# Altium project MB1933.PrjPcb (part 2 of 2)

## Sheet USB-C_Device.SchDoc: USB-C_Device
size A4; Date: Not used; ApprovedBy: Not used; CheckedBy: Not used; Author: Not used; CompanyName: STMicroelectronics; DrawnBy: Not used; Engineer: Not used; Organization: Not used; Address1: Not used; Address2: Not used; Address3: Not used; Address4: Not used; DocumentNumber: Not used; Revision: V0.1; SheetNumber: 5; SheetTotal: 11
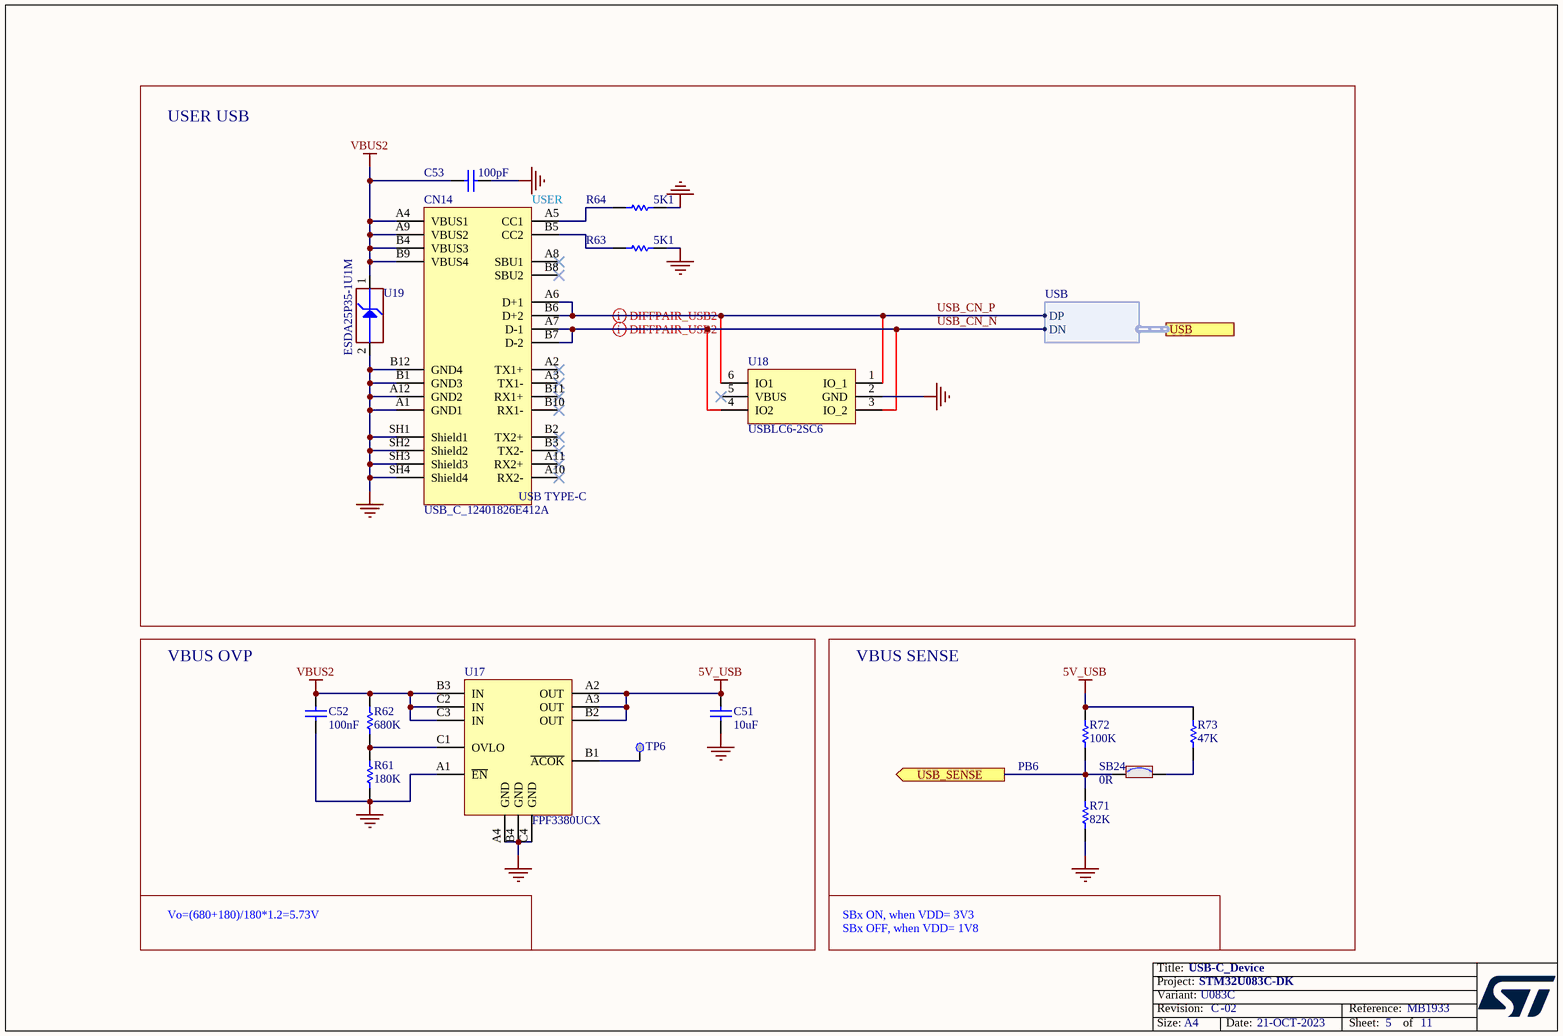
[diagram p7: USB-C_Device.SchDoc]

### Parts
C51  value 10uF  [C0603]  (hidden comment: Capacitor)
C52  value 100nF  [C0603]  (hidden comment: Capacitor)
C53  value 100pF  [C0402]  (hidden comment: Capacitor)
CN14  value USB_C_12401826E412A  [CON_USB-TYPEC_AMPHENOL_12401826E412A]  (hidden comment: USB_TYPE_C_Receptacle)
R61  value 180K  [R0402]  (hidden comment: Resistor)
R62  value 680K  [R0402]  (hidden comment: Resistor)
R63  value 5K1  [R0402]  (hidden comment: Resistor)
R64  value 5K1  [R0402]  (hidden comment: Resistor)
R71  value 82K  [R0402]  (hidden comment: Resistor)
R72  value 100K  [R0402]  (hidden comment: Resistor)
R73  value 47K  [R0402]  (hidden comment: Resistor)
SB24  value 0R  [SOLDER-BRIDGE_R0603-0R]  (hidden comment: SB_ON)
TP6  Test Point  [TP_SMD_1MM]  (value not drawn)  (no BOM)
U17  value FPF3380UCX  [ICC_WLCSP12_1P858x1P318_P040]  (hidden comment: AW329xxFCR)
U18  USBLC6-2SC6  [ESD_SOT23-6L]
U19  value ESDA25P35-1U1M  [ESD_QFN1610_2N_1K_2A]  (hidden comment: ESD-TRANSIL)

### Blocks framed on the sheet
USER USB: C53 CN14 R63 R64 U18 U19
VBUS OVP: C51 C52 R61 R62 TP6 U17
VBUS SENSE: R71-R73 SB24

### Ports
USB (harness USB), USB_SENSE (out)

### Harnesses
USB: DP, DN

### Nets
5V_USB: C51.2 R72.2 R73.2 U17.A2(OUT) U17.A3(OUT) U17.B2(OUT)
GND: C51.1 C52.2 C53.2 CN14.A1(GND1) CN14.A12(GND2) CN14.B1(GND3) CN14.B12(GND4) CN14.SH1(Shield1) CN14.SH2(Shield2) CN14.SH3(Shield3) CN14.SH4(Shield4) R61.1 R63.2 R64.2 R71.1 U17.A1(~{EN}) U17.A4(GND) U17.B4(GND) U17.C4(GND) U18.2(GND) U19.2(GND)
VBUS2: C52.1 C53.1 CN14.A4(VBUS1) CN14.A9(VBUS2) CN14.B4(VBUS3) CN14.B9(VBUS4) R62.2 U17.B3(IN) U17.C2(IN) U17.C3(IN) U19.1(IO1)
ARD_D8: R71.2 R72.1 SB24.1 ; port USB_SENSE
USB_CN_N: CN14.A7(D-1) CN14.B7(D-2) U18.3(IO_2) U18.4(IO2) ; port USB.DN  [project net PA11]
USB_CN_P: CN14.A6(D+1) CN14.B6(D+2) U18.1(IO_1) U18.6(IO1) ; port USB.DP  [project net PA12]
NetCN14_A5: CN14.A5(CC1) R64.1
NetCN14_B5: CN14.B5(CC2) R63.1
NetR61_2: R61.2 R62.1 U17.C1(OVLO)
NetR73_1: R73.1 SB24.2
NetTP6_1: TP6.1 U17.B1(~{ACOK})

Not connected (* = marked no-connect by the designer): CN14 A2(TX1+)* A3(TX1-)* A8(SBU1)* A10(RX2-)* A11(RX2+)* B2(TX2+)* B3(TX2-)* B8(SBU2)* B10(RX1-)* B11(RX1+)*; U18 5(VBUS)*

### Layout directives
differential pair; rule Impedance Constraint [Min = 85.00    Max = 95.00    ]: PA11, PA12

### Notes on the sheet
- (near CN14) USER
- PB6
- Vo=(680+180)/180*1.2=5.73V
- SBx ON, when VDD= 3V3
- SBx OFF, when VDD= 1V8

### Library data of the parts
C51 = MCD-00099: Capacitor, MLCC, 10uF, 10V, X5R, +/-10%, 0603, T=0.8mm; Part_Preference: Recommended; Manufacturer: MURATA; Manufacturer_Part_Number: GRM188R61A106KE69D; Partial_Alternate_Internal_Part_Number: MCD-03152; Order_Code_RS: 2494233; Component_Country_Of_Origin: Japan°°; ShowFields: YES; ID: 2770
C52 = MCD-01099: Capacitor, MLCC, 100nF, 50V, X7R, +/-10%, 0603, T=0.8mm; Manufacturer_Part_Number: CC0603KRX7R9BB104; Manufacturer: YAGEO; BMS_Part_Number: 9142278; Part_Preference: Recommended; Order_Code_RS: 669-8767; Component_Country_Of_Origin: China; ShowFields: YES; ID: 3397
C53 = MCD-00205: Capacitor, MLCC, 100pF, 50V, NPO, +/-5%, 0402, T=0.5mm; Part_Preference: Recommended; Manufacturer: YAGEO; Manufacturer_Part_Number: CC0402JRNPO9BN101; Component_Country_Of_Origin: China; ShowFields: YES; ID: 2658
CN14 = MCD-03232: USB_TypeC, 24 pins, RA, SMD, T=2.96mm; Part_Type: Connector; Part_Preference: Recommended; Manufacturer: AMPHENOL ICC; Manufacturer_Part_Number: 12401826E412A; Component_Country_Of_Origin: China°; ShowFields: YES; ID: 5348
R61 = MCD-00413: Resistor, 180K, 0402, +/-1%, 1/16W; Manufacturer_Part_Number: RC0402FR-07180KL; Manufacturer: YAGEO; Part_Preference: Recommended; Component_Country_Of_Origin: China; ShowFields: YES; ID: 2864
R62 = MCD-00513: Resistor, 680K, 0402, +/-1%, 1/16W; Manufacturer_Part_Number: RC0402FR-07680KL; Manufacturer: YAGEO; Part_Preference: Recommended; Component_Country_Of_Origin: China; ShowFields: YES; ID: 3227
R63 R64 = MCD-00333: Resistor, 5K1, 0402, +/-1%, 1/16W; Part_Preference: Recommended; Manufacturer: YAGEO; Manufacturer_Part_Number: RC0402FR-075K1L; Component_Country_Of_Origin: China; ShowFields: YES; ID: 2944
R71 = MCD-00531: Resistor, 82K, 0402, +/-1%, 1/16W; Part_Preference: Recommended; Manufacturer: YAGEO; Manufacturer_Part_Number: RC0402FR-0782KL; Component_Country_Of_Origin: China; ShowFields: YES; ID: 3207
R72 = MCD-00059: Resistor, 100K, 0402, +/-1%, 1/16W; Part_Preference: Recommended; Manufacturer: YAGEO; Manufacturer_Part_Number: RC0402FR-07100KL; Partial_Alternate_Internal_Part_Number: MCD-03301; Order_Code_RS: 2421891; Component_Country_Of_Origin: China; ShowFields: YES; ID: 2533
R73 = MCD-00063: Resistor, 47K, 0402, +/-1%, 1/16W; Part_Preference: Recommended; Manufacturer: YAGEO; Manufacturer_Part_Number: RC0402FR-0747KL; Order_Code_RS: 9239430; Component_Country_Of_Origin: China; ShowFields: YES; ID: 2528
SB24 = MCD-00071: Resistor, 0R, SB0603, 5%, 0.1W; Manufacturer_Part_Number: RC0603JR-070RL; Manufacturer: YAGEO; Part_Preference: Recommended; Manufacturer_HQ_COO: Unknown; ShowFields: YES; ID: 2521; Order_Code_RS: 199-5647; Component_Country_Of_Origin: China
TP6 = MCD-00074: Test Point 1mm; Part_Type: Misc; Part_Preference: Recommended; ShowFields: YES; ID: 2518; Component_Country_Of_Origin: Unknown
U17 = MCD-03166: Power switch, 28 V / 5 A  OVP with Low On-resistance, Integrated TVS; Part_Type: IC; Part_Preference: Recommended; Manufacturer: ON SEMICONDUCTOR; Partial_Alternate_Internal_Part_Number: MCD-03058; ShowFields: YES; ID: 5282; Component_Country_Of_Origin: Philippines
U18 = MCD-00163: Very low capacitance ESD protection; Part_Type: IC; Manufacturer: STMICROELECTRONICS; BMS_Part_Number: 9151075; Part_Preference: Recommended; Manufacturer_HQ_COO: EU; Component_Country_Of_Origin: China; ShowFields: YES; ID: 2707
U19 = MCD-01207: Diode, ESD TVS, 22V, 200nA, 25V8, QFN1610; Manufacturer: STMICROELECTRONICS; BMS_Part_Number: 9179045; Part_Preference: Recommended; Manufacturer_HQ_COO: EU; Component_Country_Of_Origin: China; ShowFields: YES; ID: 3289; Order_Code_RS: 163-9774

## Sheet PERIPHERAL.SchDoc: PERIPHERAL
size A4; Date: Not used; ApprovedBy: Not used; CheckedBy: Not used; Author: Not used; CompanyName: STMicroelectronics; DrawnBy: Not used; Engineer: Not used; Organization: Not used; Address1: Not used; Address2: Not used; Address3: Not used; Address4: Not used; DocumentNumber: 10; Revision: Not used; SheetNumber: 7; SheetTotal: 11
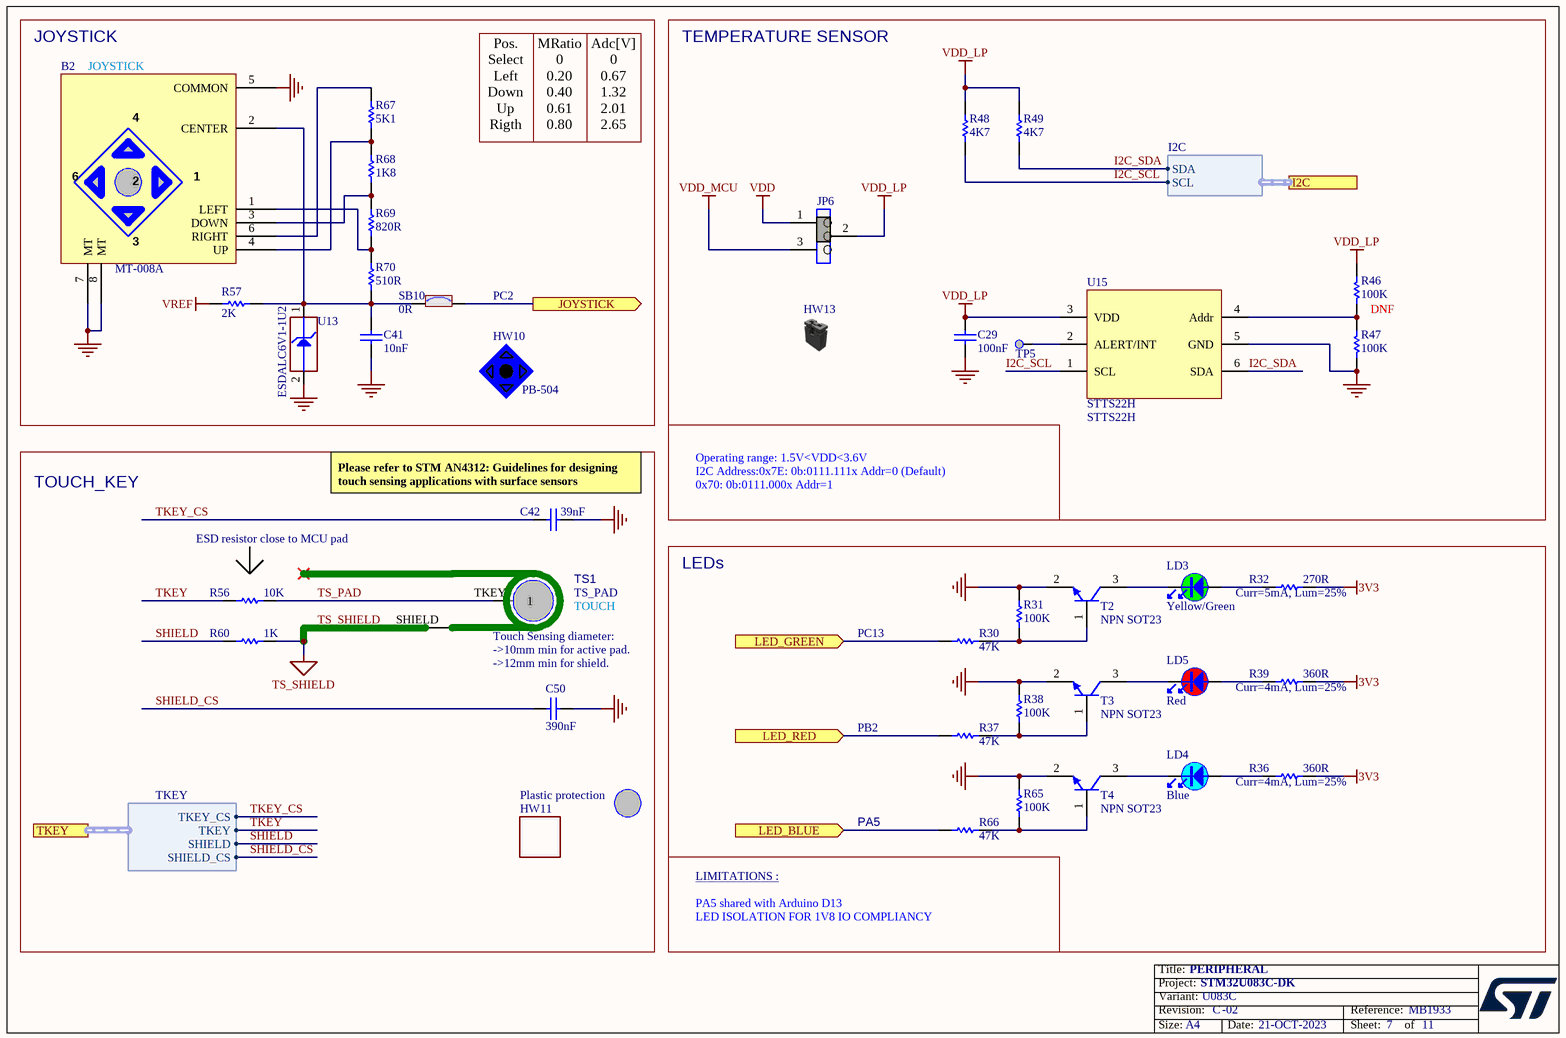
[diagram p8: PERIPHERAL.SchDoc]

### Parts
B2  value MT-008A  [SWI_XIEJIA_MT-008A_6P]  (hidden comment: Joystick MT-008A_M)
C29  value 100nF  [C0402]  (hidden comment: Capacitor)
C41  value 10nF  [C0402]  (hidden comment: Capacitor)
C42  value 39nF  [C1206_H0P85]  (hidden comment: Capacitor)
C50  value 390nF  [C0402]  (hidden comment: Capacitor)
HW10  value PB-504  (hidden comment: JOYSTICK_BLUE_HAT)  (mechanical)
HW11  value Plastic protection  (hidden comment: TouchKey sensitive Plastic protection)  (mechanical)
HW13  Shunt Black 2.54mm  (value not drawn)  (mechanical)
JP6  Jumper_Header 3x1 Fitted 1-2  [CON_SAMTEC_TSW-103-07-F-S]  (value not drawn)
LD3  value Yellow/Green  [LED_0402_EVERLIGHT_16-213SYGC/S530-E3-TR8 _YELLOW-GREEN_1A2K_H0P45]  (hidden comment: LED_green)
LD4  value Blue  [LED_0402_KINGBRIGHT_KPHHS-1005QBC-D-V_BLUE_1A2K_H0P5]  (hidden comment: LED_blue)
LD5  value Red  [LED_0402_KINGBRIGHT_KPHHS-1005SURCK_HYPER-RED_1A2K_H0P5]  (hidden comment: LED_red)
R30  value 47K  [R0402]  (hidden comment: Resistor)
R31  value 100K  [R0402]  (hidden comment: Resistor)
R32  value 270R  [R0402]  (hidden comment: Resistor)
R36  value 360R  [R0402]  (hidden comment: Resistor)
R37  value 47K  [R0402]  (hidden comment: Resistor)
R38  value 100K  [R0402]  (hidden comment: Resistor)
R39  value 360R  [R0402]  (hidden comment: Resistor)
R46  value 100K  [R0402]  (hidden comment: Resistor)
R47  value 100K  [R0402]  (hidden comment: Resistor)
R48  value 4K7  [R0402]  (hidden comment: Resistor)
R49  value 4K7  [R0402]  (hidden comment: Resistor)
R56  value 10K  [R0402]  (hidden comment: Resistor)
R57  value 2K  [R0402]  (hidden comment: Resistor)
R60  value 1K  [R0402]  (hidden comment: Resistor)
R65  value 100K  [R0402]  (hidden comment: Resistor)
R66  value 47K  [R0402]  (hidden comment: Resistor)
R67  value 5K1  [R0402]  (hidden comment: Resistor)
R68  value 1K8  [R0402]  (hidden comment: Resistor)
R69  value 820R  [R0402]  (hidden comment: Resistor)
R70  value 510R  [R0402]  (hidden comment: Resistor)
SB10  value 0R  [SOLDER-BRIDGE_R0603-0R]  (hidden comment: SB_ON)
T2  value NPN SOT23  [NPN_SOT23]  (hidden comment: 9013-SOT23)
T3  value NPN SOT23  [NPN_SOT23]  (hidden comment: 9013-SOT23)
T4  value NPN SOT23  [NPN_SOT23]  (hidden comment: 9013-SOT23)
TP5  Test Point  [TP_SMD_1MM]  (value not drawn)  (no BOM)
TS1  TS_PAD  [TSB_TOUCH-SENSING-BUTTON_TS-PAD-10_SHIELD-14]  (no BOM)
U13  value ESDALC6V1-1U2  [ESD_ST0201]  (hidden comment: ESD-TRANSIL)
U15  STTS22H  [ICC_UDFN6-EPAD_2X2_P065]

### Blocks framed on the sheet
JOYSTICK: B2 C41 HW10 R57 R67-R70 SB10 U13
TEMPERATURE SENSOR: C29 HW13 JP6 R46-R49 TP5 U15
TOUCH_KEY: C42 C50 HW11 R56 R60 TS1
LEDs: LD3-LD5 R30-R32 R36-R39 R65 R66 T2-T4

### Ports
I2C (harness I2C), JOYSTICK (out), LED_BLUE (in), LED_GREEN (in), LED_RED (in), TKEY (harness TKEY)

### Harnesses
I2C: SDA, SCL
TKEY: TKEY_CS, TKEY, SHIELD, SHIELD_CS

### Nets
3V3: R32.2 R36.2 R39.2
GND: B2.5(COMMON) B2.7(MT) B2.8(MT) C29.1 C41.1 C42.2 C50.2 R31.1 R38.1 R47.1 R65.1 T2.2(E) T3.2(E) T4.2(E) U13.2(GND) U15.5(GND)
TS_SHIELD: R60.2 TS1.SHIELD
VDD: JP6.1
VDD_LP: C29.2 JP6.2 R46.2 R48.2 R49.2 U15.3(VDD)
VDD_MCU: JP6.3
VREF: R57.1
ARD_D13: R66.1 ; port LED_BLUE
I2C_SCL: R48.1 U15.1(SCL) ; port I2C.SCL
I2C_SDA: R49.1 U15.6(SDA) ; port I2C.SDA
PB2: R37.1 ; port LED_RED
PC2: SB10.2 ; port JOYSTICK
PC13: R30.1 ; port LED_GREEN
SHIELD: R60.1 ; port TKEY.SHIELD  [project net PB12]
SHIELD_CS: C50.1 ; port TKEY.SHIELD_CS  [project net PB13]
TKEY: R56.1 ; port TKEY.TKEY  [project net PD11]
TKEY_CS: C42.1 ; port TKEY.TKEY_CS  [project net PD10]
TS_PAD: R56.2 TS1.TKEY(1)
NetB2_1: B2.1(LEFT) R69.1 R70.2
NetB2_2: B2.2(CENTER) C41.2 R57.2 R70.1 SB10.1 U13.1(IO1)
NetB2_3: B2.3(DOWN) R68.1 R69.2
NetB2_4: B2.4(UP) R67.1 R68.2
NetB2_6: B2.6(RIGHT) R67.2
NetLD3_1: LD3.1 R32.1
NetLD3_2: LD3.2 T2.3(C)
NetLD4_1: LD4.1 R36.1
NetLD4_2: LD4.2 T4.3(C)
NetLD5_1: LD5.1 R39.1
NetLD5_2: LD5.2 T3.3(C)
NetR30_2: R30.2 R31.2 T2.1(B)
NetR37_2: R37.2 R38.2 T3.1(B)
NetR46_1: R46.1 R47.2 U15.4(Addr)
NetR65_2: R65.2 R66.2 T4.1(B)
NetTP5_1: TP5.1 U15.2(ALERT/INT)

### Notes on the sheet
- (near B2) JOYSTICK
- Pos.
  Select
  Left
  Down
  Up
  Rigth
- MRatio
  0
  0.20
  0.40
  0.61
  0.80
- Adc[V]
  0
  0.67
  1.32
  2.01
  2.65
- PC2
- DNF
- (near C42) Please refer to STM AN4312: Guidelines for designing touch sensing applications with surface sensors
- I2C Address:0x7E: 0b:0111.111x Addr=0 (Default)
- 0x70: 0b:0111.000x Addr=1
- Operating range: 1.5V<VDD<3.6V
- ESD resistor close to MCU pad
- TOUCH
- PC13
- (near R32) Curr=5mA, Lum=25%
- (near TS1) Touch Sensing diameter:
  ->10mm min for active pad.
  ->12mm min for shield.
- (near R39) Curr=4mA, Lum=25%
- PB2
- (near R36) Curr=4mA, Lum=25%
- PA5
- LED ISOLATION FOR 1V8 IO COMPLIANCY
- PA5 shared with Arduino D13
- LIMITATIONS :

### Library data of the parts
B2 = MCD-00132: Joystick, Black hat; BMS_Part_Number: 9180124; Part_Preference: Recommended; Part_Type: Misc; Manufacturer: XIEJIA ELECTRONICS; Component_Country_Of_Origin: Unknown; ShowFields: YES; ID: 2736
C29 = MCD-00006: Capacitor, MLCC, 100nF, 16V, X7R, +/-10%, 0402, T=0.5mm; Manufacturer_Part_Number: CC0402KRX7R7BB104; Manufacturer: YAGEO; Part_Preference: Recommended; Partial_Alternate_Internal_Part_Number: MCD-03299; Order_Code_RS: 9402047; Component_Country_Of_Origin: China; ShowFields: YES; ID: 2474
C41 = MCD-02198: Capacitor, MLCC, 10nF, 50V, X7R, +/-10%, 0402, T=0.5mm; Manufacturer_Part_Number: CC0402KRX7R9BB103; Manufacturer: YAGEO; Part_Preference: Recommended; Order_Code_RS: 6169644; Component_Country_Of_Origin: China; ShowFields: YES; ID: 4298
C42 = MCD-01939: Capacitor, MLCC, 39nF, 50V, COG, +/-5%, 1206, T=0.85mm; Manufacturer_Part_Number: GRM3195C1H393JA01D; Manufacturer: MURATA; Part_Preference: Recommended; Component_Country_Of_Origin: Japan; ShowFields: YES; ID: 4039
C50 = MCD-02154: Capacitor, MLCC, 390nF, 10V, X5R, +/-10%, 0402, T=0.5mm; Manufacturer_Part_Number: GMD155R61A394KE11J; Manufacturer: MURATA; Part_Preference: Recommended; Order_Code_RS: N\A; Component_Country_Of_Origin: Japan; ShowFields: YES; ID: 4254
HW10 = MCD-01337: Joystick, Blue hat; Part_Type: Misc; Manufacturer: JIUBABA; Part_Preference: Alternate; Component_Country_Of_Origin: Unknown; Alternate_EMS: A; ShowFields: YES; ID: 3437
HW11 = MCD-01201: Plastic protection for Sensitive Touch Key: square 14mmx14mmx1mm; Part_Type: Misc; Part_Preference: Recommended; ShowFields: YES; ID: 3295
HW13 = MCD-00043: Shunt, 2.54mm, Black, 4.3A, 6.1mm, 5mR; Manufacturer_Part_Number: SNT-100-BK-G; Manufacturer: SAMTEC; Part_Type: Misc; Part_Preference: Recommended; Full_Alternate_Internal_Part_Number: MCD-02388; Manufacturer_HQ_COO: Unknown; Partial_Alternate_Internal_Part_Number: MCD-01849; Value: SNT-100-BK-G; Component_Country_Of_Origin: China, Costa Rica, Malaysia, USA, Vietnam; ShowFields: YES; ID: 2551; Order_Code_RS: 158-7784; Alternate_EMS: A
JP6 = MCD-00684: Header, 3x1, 2.54mm, VR, TH, T=5.84mm/2.54mm; Part_Type: Connector; Part_Preference: Recommended; Manufacturer: SAMTEC; Manufacturer_Part_Number: TSW-103-07-F-S; Partial_Alternate_Internal_Part_Number: MCD-03595, MCD-03723; Order_Code_RS: 161-2248; Component_Country_Of_Origin: China, Costa Rica, Malaysia, United States, Vietnam; Alternate_EMS: A; ShowFields: YES; ID: 3059
LD3 = MCD-02330: LED Bicolor, Yellow/Green, 2V, 25mA, 0402; Part_Type: Display; Manufacturer_Part_Number: 16-213SYGC/S530-E3/TR8; Manufacturer: EVERLIGHT; Part_Preference: Recommended; Component_Country_Of_Origin: China; ShowFields: YES; ID: 4436
LD4 = MCD-00706: LED, Blue, 3V3, 20mA, 0402; Part_Type: Display; Manufacturer_Part_Number: KPHHS-1005QBC-D-V; Manufacturer: KINGBRIGHT; Part_Preference: Recommended; Component_Country_Of_Origin: Unknown; ShowFields: YES; ID: 3040; Order_Code_RS: 146-1490
LD5 = MCD-00708: LED, Red, 1V95, 20mA, 0402; Part_Type: Display; Manufacturer_Part_Number: KPHHS-1005SURCK; Manufacturer: KINGBRIGHT; Part_Preference: Recommended; Component_Country_Of_Origin: Unknown; ShowFields: YES; ID: 3037; Order_Code_RS: 466-3633
R30 R37 R66 = MCD-00063: Resistor, 47K, 0402, +/-1%, 1/16W; Manufacturer_Part_Number: RC0402FR-0747KL; Manufacturer: YAGEO; Part_Preference: Recommended; Order_Code_RS: 9239430; Component_Country_Of_Origin: China; ShowFields: YES; ID: 2528
R31 R38 R46 R47 R65 = MCD-00059: Resistor, 100K, 0402, +/-1%, 1/16W; Manufacturer_Part_Number: RC0402FR-07100KL; Manufacturer: YAGEO; Part_Preference: Recommended; Partial_Alternate_Internal_Part_Number: MCD-03301; Order_Code_RS: 2421891; Component_Country_Of_Origin: China; ShowFields: YES; ID: 2533
R32 = MCD-00441: Resistor, 270R, 0402, +/-1%, 1/16W; Manufacturer_Part_Number: RC0402FR-07270RL; Manufacturer: YAGEO; Part_Preference: Recommended; Component_Country_Of_Origin: China; ShowFields: YES; ID: 2838
R36 R39 = MCD-00461: Resistor, 360R, 0402, +/-1%, 1/16W; Manufacturer_Part_Number: RC0402FR-07360RL; Manufacturer: YAGEO; Part_Preference: Recommended; Component_Country_Of_Origin: China; ShowFields: YES; ID: 2816
R48 R49 = MCD-00065: Resistor, 4K7, 0402, +/-1%, 1/16W; Manufacturer_Part_Number: RC0402FR-074K7L; Manufacturer: YAGEO; Part_Preference: Recommended; Partial_Alternate_Internal_Part_Number: MCD-03300; Order_Code_RS: 9239316; Component_Country_Of_Origin: China; ShowFields: YES; ID: 2526
R56 = MCD-00053: Resistor, 10K, 0402, +/-1%, 1/16W; Manufacturer_Part_Number: RC0402FR-0710KL; Manufacturer: YAGEO; BMS_Part_Number: 9131590; Part_Preference: Recommended; Order_Code_RS: 9239359; Component_Country_Of_Origin: China; ShowFields: YES; ID: 2539
R57 = MCD-00419: Resistor, 2K, 0402, +/-1%, 1/16W; Manufacturer_Part_Number: RC0402FR-072KL; Manufacturer: YAGEO; Part_Preference: Recommended; Component_Country_Of_Origin: China; ShowFields: YES; ID: 2861
R60 = MCD-00061: Resistor, 1K, 0402, +/-1%,1/16W; Manufacturer_Part_Number: RC0402FR-071KL; Manufacturer: YAGEO; Part_Preference: Recommended; Order_Code_RS: 9239235; Component_Country_Of_Origin: China; ShowFields: YES; ID: 2532
R67 = MCD-00333: Resistor, 5K1, 0402, +/-1%, 1/16W; Manufacturer_Part_Number: RC0402FR-075K1L; Manufacturer: YAGEO; Part_Preference: Recommended; Component_Country_Of_Origin: China; ShowFields: YES; ID: 2944
R68 = MCD-00409: Resistor, 1K8, 0402, +/-1%, 1/16W; Manufacturer_Part_Number: RC0402FR-071K8L; Manufacturer: YAGEO; Part_Preference: Recommended; Component_Country_Of_Origin: China; ShowFields: YES; ID: 2871
R69 = MCD-00527: Resistor, 820R, 0402, +/-1%, 1/16W; Manufacturer_Part_Number: RC0402FR-07820RL; Manufacturer: YAGEO; Part_Preference: Recommended; Component_Country_Of_Origin: China; ShowFields: YES; ID: 3217
R70 = MCD-00064: Resistor, 510R, 0402, +/-1%, 1/16W; Manufacturer_Part_Number: RC0402FR-07510RL; Manufacturer: YAGEO; Part_Preference: Recommended; Order_Code_RS: 1458804; Component_Country_Of_Origin: China; ShowFields: YES; ID: 2525
SB10 = MCD-00071: as SB24 on sheet USB-C_Device
T2-T4 = MCD-00073: NPN Bipolar Transistor; Part_Type: IC; Manufacturer_Part_Number: BSR14; Manufacturer: ON SEMICONDUCTOR; Part_Preference: Recommended; Partial_Alternate_Internal_Part_Number: MCD-01737, MCD-03305, , MCD-02988; Component_Country_Of_Origin: Unknown; ShowFields: YES; ID: 2519
TP5 = MCD-00074: as TP6 on sheet USB-C_Device
TS1 = MCD-01194: -Touch Sensing button: diameter 10mm min,  active shield diameter 12mm min; Part_Type: Misc; Manufacturer_Part_Number: Touch_sensing_Button; Part_Preference: Recommended; ShowFields: YES; ID: 3303
U13 = MCD-00170: Diode, ESD TVS, 3V, 100nA, 8V, ST0201; Manufacturer: STMICROELECTRONICS; BMS_Part_Number: 9151132; Part_Preference: Recommended; Manufacturer_HQ_COO: EU; Component_Country_Of_Origin: China; ShowFields: YES; ID: 2696; Order_Code_RS: 795-8404
U15 = MCD-02159: MEMS, Low-voltage, ultra-low-power, 0.5°C accuracy I2C/SMBus 3.0 temperature sensor; Part_Type: IC; Part_Preference: Recommended; Manufacturer: STMICROELECTRONICS; Manufacturer_HQ_COO: EU; Order_Code_RS: 194-7646; Component_Country_Of_Origin: Thailand; ShowFields: YES; ID: 4259

## Sheet STM32_microcontroller_power.SchDoc: STM32 microcontroller power
size A4; Date: Not used; ApprovedBy: Not used; CheckedBy: Not used; Author: Not used; CompanyName: STMicroelectronics; DrawnBy: Not used; Engineer: Not used; Organization: Not used; Address1: Not used; Address2: Not used; Address3: Not used; Address4: Not used; DocumentNumber: Not used; Revision: Not used; SheetNumber: 4; SheetTotal: 11
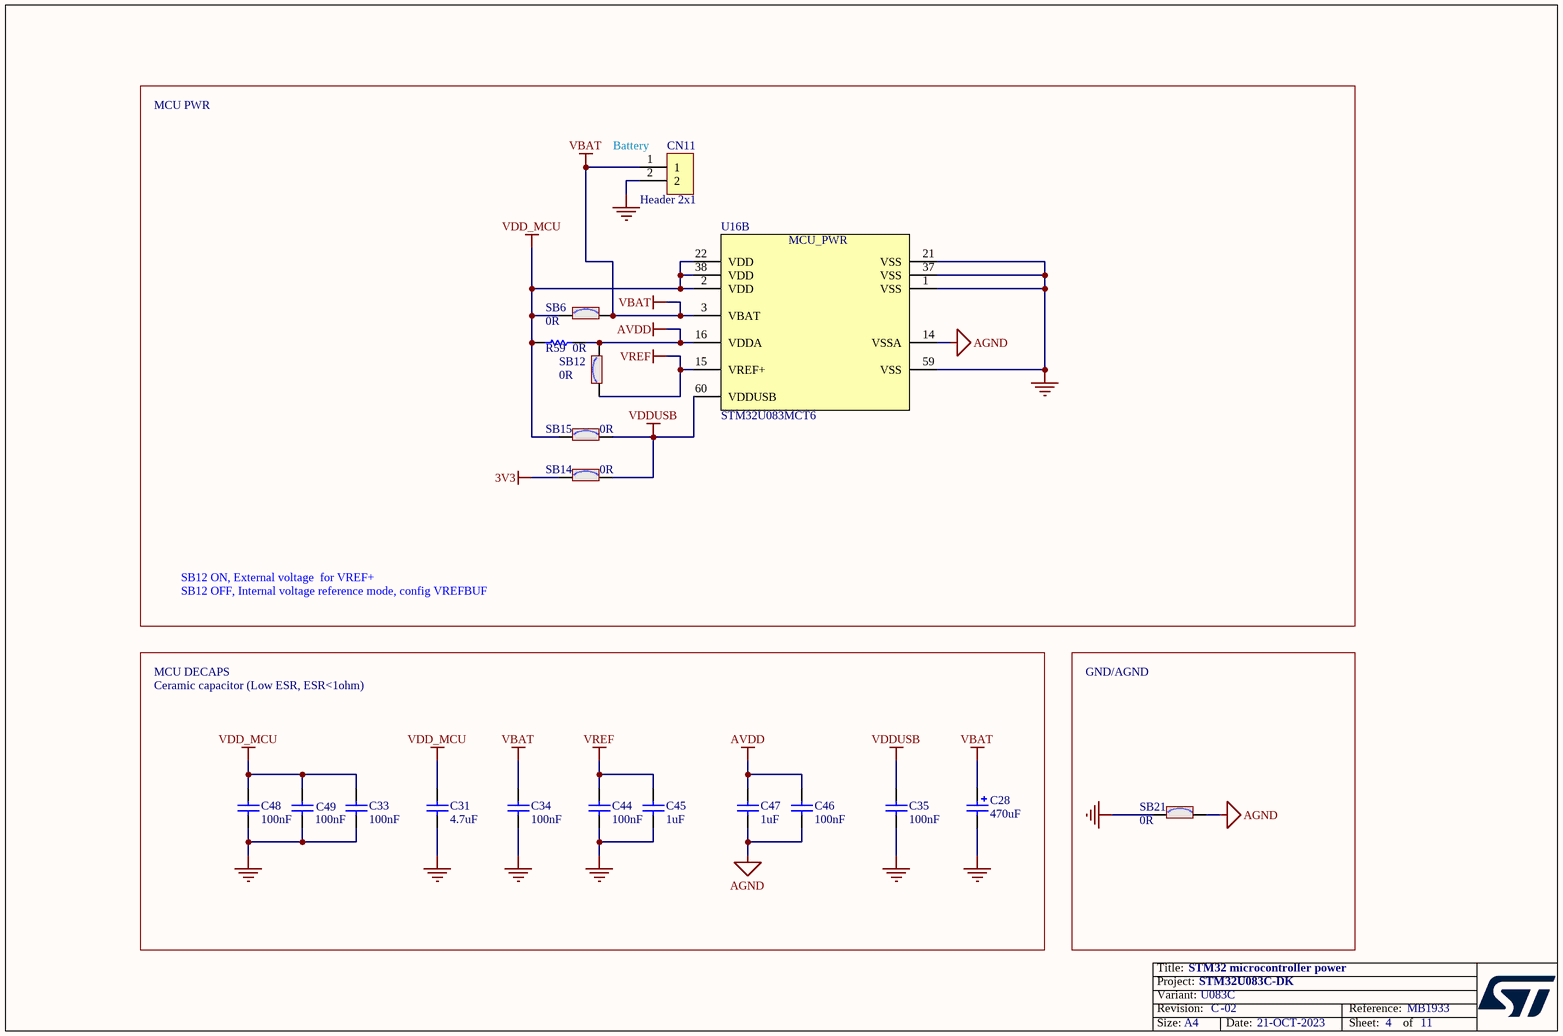
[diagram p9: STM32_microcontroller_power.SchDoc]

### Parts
C28  value 470uF  [CPOL_TDK_B41888C5477M000_H16]  (hidden comment: Cap_POL_TANA)
C31  value 4.7uF  [C0603_H0P8]  (hidden comment: Capacitor)
C33  value 100nF  [C0402]  (hidden comment: Capacitor)
C34  value 100nF  [C0402]  (hidden comment: Capacitor)
C35  value 100nF  [C0402]  (hidden comment: Capacitor)
C44  value 100nF  [C0402]  (hidden comment: Capacitor)
C45  value 1uF  [C0603]  (hidden comment: Capacitor)
C46  value 100nF  [C0402]  (hidden comment: Capacitor)
C47  value 1uF  [C0603]  (hidden comment: Capacitor)
C48  value 100nF  [C0402]  (hidden comment: Capacitor)
C49  value 100nF  [C0402]  (hidden comment: Capacitor)
CN11  Header 2x1  [CON_SAMTEC_TSW-102-07-G-S]
R59  value 0R  [R0603]  (hidden comment: Resistor)
SB6  value 0R  [SOLDER-BRIDGE_R0603-0R]  (hidden comment: SB_ON)
SB12  value 0R  [SOLDER-BRIDGE_R0603-0R]  (hidden comment: SB_ON)
SB14  value 0R  [SOLDER-BRIDGE_R0603-0R]  (hidden comment: SB_ON)
SB15  value 0R  [SOLDER-BRIDGE_R0603-0R]  (hidden comment: SB_ON)
SB21  value 0R  [SOLDER-BRIDGE_R0603-0R]  (hidden comment: SB_ON)
U16  STM32U083MCT6  [ICC_LQFP80_12X12_P050_SOCKET_YAMAICHI_IC149-080-130-B5]  (part B of 2)

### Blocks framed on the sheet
GND/AGND: SB21

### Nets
3V3: SB14.1
AGND: C46.1 C47.2 SB21.2 U16.14(VSSA)
AVDD: C46.2 C47.1 R59.2 SB12.2 U16.16(VDDA)
GND: C28.2 C31.1 C33.1 C34.1 C35.1 C44.1 C45.2 C48.1 C49.1 CN11.2 SB21.1 U16.1(VSS) U16.21(VSS) U16.37(VSS) U16.59(VSS)
VBAT: C28.1 C34.2 CN11.1 SB6.2 U16.3(VBAT)
VDD_MCU: C31.2 C33.2 C48.2 C49.2 R59.1 SB6.1 SB15.1 U16.2(VDD) U16.22(VDD) U16.38(VDD)
VDDUSB: C35.2 SB14.2 SB15.2 U16.60(VDDUSB)
VREF: C44.2 C45.1 SB12.1 U16.15(VREF+)

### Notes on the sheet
- MCU PWR
- (near CN11) Battery
- SB12 ON, External voltage  for VREF+
- SB12 OFF, Internal voltage reference mode, config VREFBUF
- MCU DECAPS
- Ceramic capacitor (Low ESR, ESR<1ohm)

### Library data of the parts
C28 = MCD-03332: Capacitor, Electrolytic Low ESR, 470uF, 25V, 0R06, +/-20%, TH, Radial pitch 5mm, D=10mm, T=16mm; Part_Preference: Recommended; Manufacturer: TDK; Manufacturer_Part_Number: B41888C5477M000; Order_Code_RS: 241-6703; Component_Country_Of_Origin: Brazil°; ShowFields: YES; ID: 5448
C31 = MCD-01721: Capacitor, MLCC, 4.7uF, 10V, X5R, +/-10%, 0603, T=0.8mm; Part_Preference: Recommended; Manufacturer: YAGEO; Manufacturer_Part_Number: CC0603KRX5R6BB475; Component_Country_Of_Origin: China; ShowFields: YES; ID: 3821
C33-C35 C44 C46 C48 C49 = MCD-00006: as C29 on sheet PERIPHERAL
C45 C47 = MCD-00010: Capacitor, MLCC, 1uF, 16V, X5R, +/-10%, 0603, T=0.8mm; Manufacturer_Part_Number: CC0603KRX5R7BB105; Manufacturer: YAGEO; Part_Preference: Recommended; Order_Code_RS: 2370680; Component_Country_Of_Origin: China; ShowFields: YES; ID: 2470
CN11 = MCD-00032: Header, 2x1, 2.54mm, VR, TH, T=5.84mm/2.54mm; Part_Type: Connector; Manufacturer_Part_Number: TSW-102-07-G-S; Manufacturer: SAMTEC; Part_Preference: Recommended; Order_Code_RS: 2505044; Component_Country_Of_Origin: China, Costa Rica, Malaysia, USA, Vietnam; ShowFields: YES; ID: 2484
R59 = MCD-00056: Resistor, 0R, 0603, +/-5%, 1/10W; Manufacturer_Part_Number: RC0603JR-070RL; Manufacturer: YAGEO; Part_Preference: Recommended; Order_Code_RS: 9233130RL; Component_Country_Of_Origin: China; ShowFields: YES; ID: 2536
SB6 SB12 SB14 SB15 SB21 = MCD-00071: as SB24 on sheet USB-C_Device
U16 = MCD-03131: Arm® Cortex®-M0+ 32-bit MCU,  256K Flash memory, with LQFP80 socket footprint (IC149-080-130-B5); Part_Type: IC; Part_Preference: Recommended; Manufacturer: STMICROELECTRONICS; Component_Country_Of_Origin: Unknown; ShowFields: YES; ID: 5247

## Sheet Arduino_Mikrobus_connectors.SchDoc: Connectors
size A4; CompanyName: STMicroelectronics; Organization: Microcontrollers Division; SheetNumber: 8; SheetTotal: 11
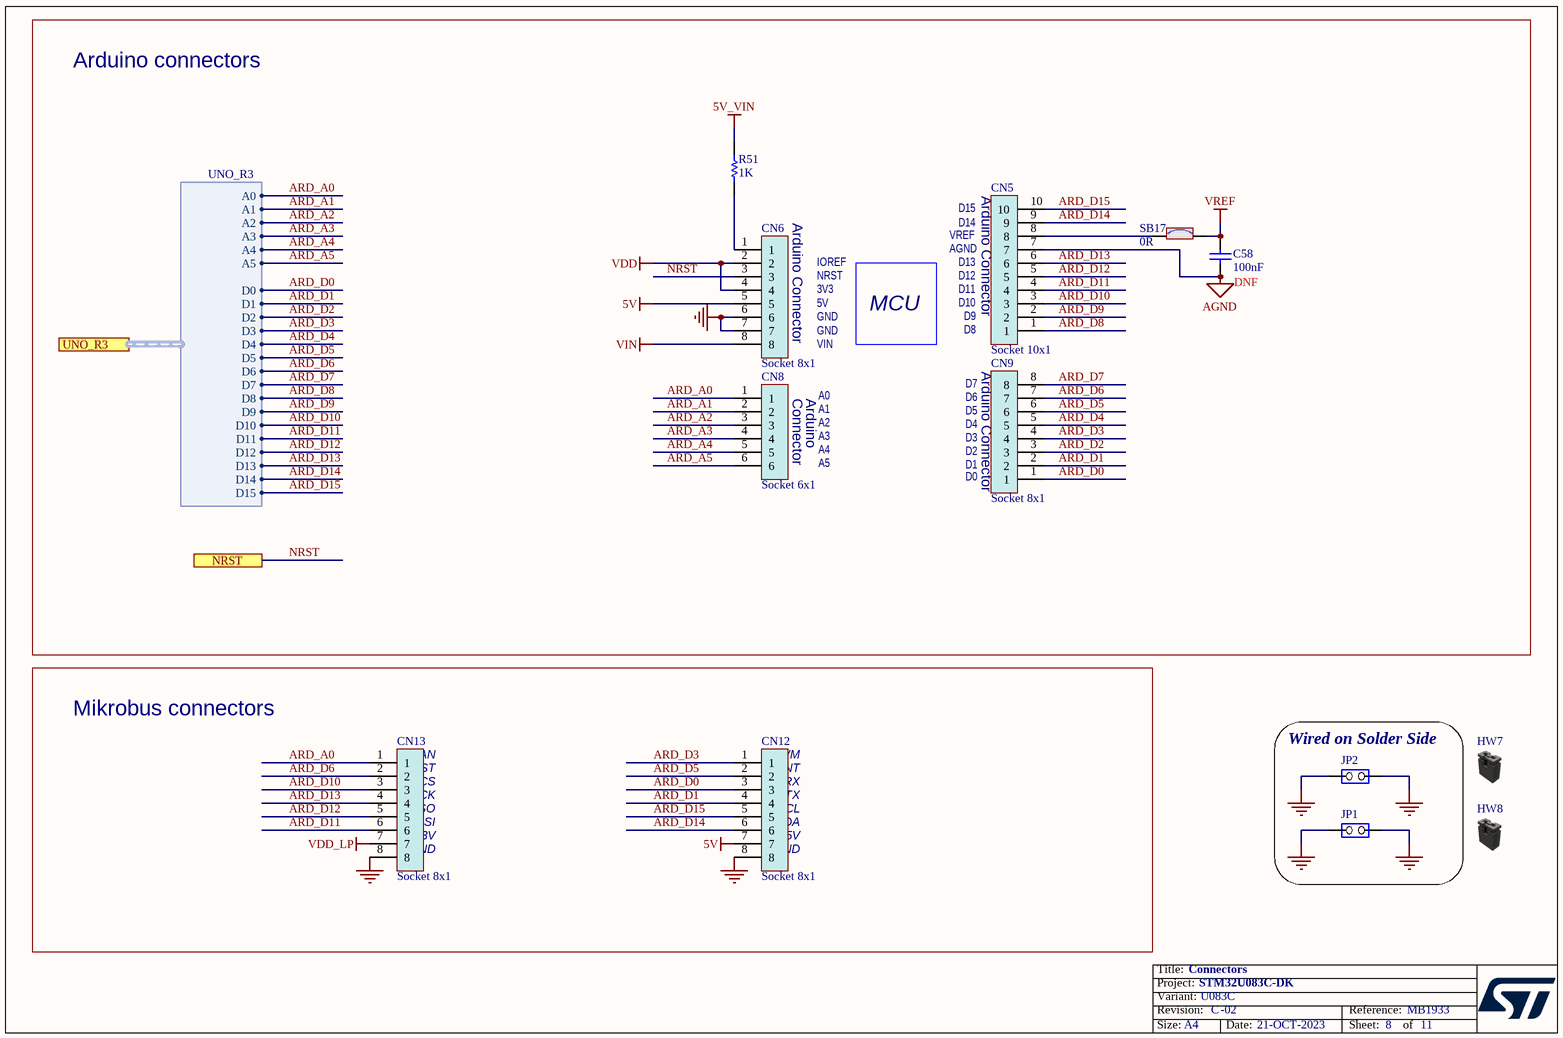
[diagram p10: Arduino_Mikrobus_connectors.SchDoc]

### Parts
C58  value 100nF  [C0402]  (hidden comment: Capacitor)
CN5  Socket 10x1  [CON_SAMTEC_SSW-110-01-X-S]
CN6  Socket 8x1  [CON_SAMTEC_SSW-108-01-X-S]
CN8  Socket 6x1  [CON_SAMTEC_SSW-106-01-X-S]
CN9  Socket 8x1  [CON_SAMTEC_SSW-108-01-X-S]
CN12  Socket 8x1  [CON_SAMTEC_SSW-108-01-X-S]
CN13  Socket 8x1  [CON_SAMTEC_SSW-108-01-X-S]
HW7  Shunt Black 2.54mm  (value not drawn)  (mechanical)
HW8  Shunt Black 2.54mm  (value not drawn)  (mechanical)
JP1  Jumper_Header 2x1  [CON_SAMTEC_TSW-102-09-X-S]  (value not drawn)
JP2  Jumper_Header 2x1  [CON_SAMTEC_TSW-102-09-X-S]  (value not drawn)
R51  value 1K  [R0402]  (hidden comment: Resistor)
SB17  value 0R  [SOLDER-BRIDGE_R0603-0R]  (hidden comment: SB_ON)

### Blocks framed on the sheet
Mikrobus connectors: CN12 CN13
Wired on Solder Side: JP1 JP2

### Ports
NRST, UNO_R3 (harness UNO_R3)

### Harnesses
UNO_R3: A0, A1, A2, A3, A4, A5, D0, D1, D2, D3, D4, D5, D6, D7, D8, D9, D10, D11, D12, D13, D14, D15

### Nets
5V: CN6.5 CN12.7
5V_VIN: R51.1
AGND: C58.1 CN5.7
GND: CN6.6 CN6.7 CN12.8 CN13.8 JP1.1(COMMON) JP1.2(NO) JP2.1(COMMON) JP2.2(NO)
VDD: CN6.2 CN6.4
VDD_LP: CN13.7
VIN: CN6.8
VREF: C58.2 SB17.2
ARD_A0: CN8.1 CN13.1 ; port UNO_R3.A0
ARD_A1: CN8.2 ; port UNO_R3.A1
ARD_A2: CN8.3 ; port UNO_R3.A2
ARD_A3: CN8.4 ; port UNO_R3.A3
ARD_A4: CN8.5 ; port UNO_R3.A4
ARD_A5: CN8.6 ; port UNO_R3.A5
ARD_D0: CN9.1 CN12.3 ; port UNO_R3.D0
ARD_D1: CN9.2 CN12.4 ; port UNO_R3.D1
ARD_D2: CN9.3 ; port UNO_R3.D2
ARD_D3: CN9.4 CN12.1 ; port UNO_R3.D3
ARD_D4: CN9.5 ; port UNO_R3.D4
ARD_D5: CN9.6 CN12.2 ; port UNO_R3.D5
ARD_D6: CN9.7 CN13.2 ; port UNO_R3.D6
ARD_D7: CN9.8 ; port UNO_R3.D7
ARD_D8: CN5.1 ; port UNO_R3.D8
ARD_D9: CN5.2 ; port UNO_R3.D9
ARD_D10: CN5.3 CN13.3 ; port UNO_R3.D10
ARD_D11: CN5.4 CN13.6 ; port UNO_R3.D11
ARD_D12: CN5.5 CN13.5 ; port UNO_R3.D12
ARD_D13: CN5.6 CN13.4 ; port UNO_R3.D13
ARD_D14: CN5.9 CN12.6 ; port UNO_R3.D14
ARD_D15: CN5.10 CN12.5 ; port UNO_R3.D15
NRST: CN6.3 ; port NRST
NetCN5_8: CN5.8 SB17.1
NetCN6_1: CN6.1 R51.2

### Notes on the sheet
- Arduino connectors
- (near CN6) Arduino Connector
- (near CN5) VREF
- (near CN5) AGND
- (near CN5) D14
- (near CN5) D15
- (near CN5) Arduino Connector
- 5V
- 3V3
- NRST
- IOREF
- MCU
- (near CN5) D10
- (near CN5) D11
- (near CN5) D12
- (near CN5) D13
- (near C58) DNF
- GND
- VIN
- (near CN5) D9
- D8
- D7
- (near CN9) Arduino Connector
- (near CN8) Connector
- (near CN8) Arduino
- A0
- A1
- A2
- A3
- A4
- (near CN9) D3
- (near CN9) D4
- (near CN9) D5
- (near CN9) D6
- A5
- (near CN9) D0
- (near CN9) D1
- (near CN9) D2
- (near CN13) AN
- (near CN13) RST
- (near CN13) CS
- (near CN12) PWM
- (near CN12) INT
- (near CN12) RX
- (near CN13) SCK
- (near CN13) MISO
- (near CN13) MOSI
- (near CN13) +3.3V
- (near CN13) GND
- (near CN12) TX
- (near CN12) SCL
- (near CN12) SDA
- (near CN12) +5V
- (near CN12) GND

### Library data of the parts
C58 = MCD-00006: as C29 on sheet PERIPHERAL
CN5 = MCD-02080: Socket, 10x1, 2.54mm, VR, TH, T=8.51/2.64mm; Manufacturer_Part_Number: SSW-110-01-G-S; Manufacturer: SAMTEC; Part_Type: Connector; Part_Preference: Recommended; Partial_Alternate_Internal_Part_Number: MCD-03160; Order_Code_RS: 765-5736; Component_Country_Of_Origin: China, Costa Rica, Malaysia, United States, Vietnam; ShowFields: YES; ID: 4180
CN6 = MCD-01743: Socket, 8x1, 2.54mm, VR, TH, T=8.51/2.64mm; Manufacturer_Part_Number: SSW-108-01-G-S; Manufacturer: SAMTEC; Part_Type: Connector; Part_Preference: Recommended; Partial_Alternate_Internal_Part_Number: MCD-03161; Order_Code_RS: 765-5698; Component_Country_Of_Origin: China, Costa Rica, Malaysia, United States, Vietnam; ShowFields: YES; ID: 3843
CN8 = MCD-02079: Socket, 6x1, 2.54mm, VR, TH, T=8.51/2.64mm; Part_Type: Connector; Manufacturer_Part_Number: SSW-106-01-G-S; Manufacturer: SAMTEC; Part_Preference: Recommended; Partial_Alternate_Internal_Part_Number: MCD-03162; Order_Code_RS: 765-5666; Component_Country_Of_Origin: China, Costa Rica, Malaysia, United States, Vietnam; ShowFields: YES; ID: 4179
CN9 CN12 CN13 = MCD-01743: Socket, 8x1, 2.54mm, VR, TH, T=8.51/2.64mm; Part_Type: Connector; Manufacturer_Part_Number: SSW-108-01-G-S; Manufacturer: SAMTEC; Part_Preference: Recommended; Partial_Alternate_Internal_Part_Number: MCD-03161; Order_Code_RS: 765-5698; Component_Country_Of_Origin: China, Costa Rica, Malaysia, United States, Vietnam; ShowFields: YES; ID: 3843
HW7 HW8 = MCD-00043: Shunt, 2.54mm, Black, 4.3A, 6.1mm, 5mR; Part_Type: Misc; Manufacturer_Part_Number: SNT-100-BK-G; Manufacturer: SAMTEC; Part_Preference: Recommended; Full_Alternate_Internal_Part_Number: MCD-02388; Manufacturer_HQ_COO: Unknown; Partial_Alternate_Internal_Part_Number: MCD-01849; Value: SNT-100-BK-G; Component_Country_Of_Origin: China, Costa Rica, Malaysia, USA, Vietnam; ShowFields: YES; ID: 2551; Order_Code_RS: 158-7784; Alternate_EMS: A
JP1 JP2 = MCD-00214: Header, 2x1, 2.54mm, VR, TH, T=5.84mm/10.16mm; Part_Type: Connector; Manufacturer_Part_Number: TSW-102-09-G-S; Manufacturer: SAMTEC; Part_Preference: Recommended; Full_Alternate_Internal_Part_Number: MCD-02393; Partial_Alternate_Internal_Part_Number: MCD-03591, MCD-03719; Order_Code_RS: 180-3129; Component_Country_Of_Origin: China, Costa Rica, Malaysia, United States, Vietnam; ShowFields: YES; ID: 2652; Alternate_EMS: A
R51 = MCD-00061: as R60 on sheet PERIPHERAL
SB17 = MCD-00071: as SB24 on sheet USB-C_Device

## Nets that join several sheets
3V3: Power (C20.2 C22.2 R44.1 U10.5), PERIPHERAL (R32.2 R36.2 R39.2), STM32_microcontroller_power (SB14.1)
5V: STM32_microcontroller_IOs (CN7.20), Power (5 pins), STLINK_V2EC (D2.1 R4.2), Arduino_Mikrobus_connectors (CN6.5 CN12.7)
5V_STLK: Power (JP3.1), STLINK_V2EC (C11.2 U7.1)
5V_USB: Power (JP3.5), USB-C_Device (6 pins)
5V_VIN: Power (C32.2 JP3.7 U14.2 U14.4), Arduino_Mikrobus_connectors (R51.1)
AGND: STM32_microcontroller_IOs (CN10.11), STM32_microcontroller_power (C46.1 C47.2 SB21.2 U16.14), Arduino_Mikrobus_connectors (C58.1 CN5.7)
AVDD: STM32_microcontroller_IOs (CN10.9), STM32_microcontroller_power (5 pins)
E5V: STM32_microcontroller_IOs (CN7.6), Power (JP3.3)
GND: STM32_microcontroller_IOs (14 pins), Power (18 pins), STLINK_V2EC (67 pins), USB-C_Device (21 pins), PERIPHERAL (16 pins), STM32_microcontroller_power (15 pins), Arduino_Mikrobus_connectors (8 pins)
VBAT: STM32_microcontroller_IOs (CN7.35), STM32_microcontroller_power (5 pins)
VBUS_STLK: Power (JP3.9), STLINK_V2EC (11 pins)
VDD: STM32_microcontroller_IOs (CN7.18 R58.1), Power (6 pins), STLINK_V2EC (8 pins), PERIPHERAL (JP6.1), Arduino_Mikrobus_connectors (CN6.2 CN6.4)
VDD_LP: PERIPHERAL (6 pins), Arduino_Mikrobus_connectors (CN13.7)
VDD_MCU: STM32_microcontroller_IOs (CN7.14), Power (JP7.1), PERIPHERAL (JP6.3), STM32_microcontroller_power (10 pins)
VDDUSB: STM32_microcontroller_IOs (CN7.7), STM32_microcontroller_power (C35.2 SB14.2 SB15.2 U16.60)
VIN: Power (C30.2 U14.3), Arduino_Mikrobus_connectors (CN6.8)
VREF: STM32_microcontroller_IOs (CN10.10), PERIPHERAL (R57.1), STM32_microcontroller_power (C44.2 C45.1 SB12.1 U16.15), Arduino_Mikrobus_connectors (C58.2 SB17.2)
ARD_A0: STM32_microcontroller_IOs (CN7.30 U16.17), Arduino_Mikrobus_connectors (CN8.1 CN13.1)
ARD_A1: STM32_microcontroller_IOs (CN7.32 U16.18), Arduino_Mikrobus_connectors (CN8.2)
ARD_A2: STM32_microcontroller_IOs (CN7.34 U16.23), Arduino_Mikrobus_connectors (CN8.3)
ARD_A3: STM32_microcontroller_IOs (CN7.36 U16.29), Arduino_Mikrobus_connectors (CN8.4)
ARD_A4: STM32_microcontroller_IOs (CN7.38 U16.11), Arduino_Mikrobus_connectors (CN8.5)
ARD_A5: STM32_microcontroller_IOs (CN7.40 U16.10), Arduino_Mikrobus_connectors (CN8.6)
ARD_D0: STM32_microcontroller_IOs (CN10.39 U16.20), STLINK_V2EC (CN4.13 R33.2 U9.3), Arduino_Mikrobus_connectors (CN9.1 CN12.3)
ARD_D1: STM32_microcontroller_IOs (CN10.37 U16.19), STLINK_V2EC (CN4.14 R27.2 U9.1), Arduino_Mikrobus_connectors (CN9.2 CN12.4)
ARD_D2: STM32_microcontroller_IOs (CN10.35 U16.65), Arduino_Mikrobus_connectors (CN9.3)
ARD_D3: STM32_microcontroller_IOs (CN10.33 U16.73), Arduino_Mikrobus_connectors (CN9.4 CN12.1)
ARD_D4: STM32_microcontroller_IOs (CN10.31 U16.75), Arduino_Mikrobus_connectors (CN9.5)
ARD_D5: STM32_microcontroller_IOs (CN10.29 U16.74), Arduino_Mikrobus_connectors (CN9.6 CN12.2)
ARD_D6: STM32_microcontroller_IOs (CN10.27 U16.35), Arduino_Mikrobus_connectors (CN9.7 CN13.2)
ARD_D7: STM32_microcontroller_IOs (CN10.25 U16.68), Arduino_Mikrobus_connectors (CN9.8)
ARD_D8: STM32_microcontroller_IOs (CN10.23 U16.76), USB-C_Device (R71.2 R72.1 SB24.1), Arduino_Mikrobus_connectors (CN5.1)
ARD_D9: STM32_microcontroller_IOs (CN10.21 U16.50), Arduino_Mikrobus_connectors (CN5.2)
ARD_D10: STM32_microcontroller_IOs (CN10.19 U16.62), Arduino_Mikrobus_connectors (CN5.3 CN13.3)
ARD_D11: STM32_microcontroller_IOs (CN10.17 U16.26), Arduino_Mikrobus_connectors (CN5.4 CN13.6)
ARD_D12: STM32_microcontroller_IOs (CN10.15 U16.25), Arduino_Mikrobus_connectors (CN5.5 CN13.5)
ARD_D13: STM32_microcontroller_IOs (CN10.13 U16.24), PERIPHERAL (R66.1), Arduino_Mikrobus_connectors (CN5.6 CN13.4)
ARD_D14: STM32_microcontroller_IOs (CN10.7 SB4.1 U16.77), Arduino_Mikrobus_connectors (CN5.9 CN12.6)
ARD_D15: STM32_microcontroller_IOs (CN10.5 SB5.1 U16.79), Arduino_Mikrobus_connectors (CN5.10 CN12.5)
COM0: STM32_microcontroller_IOs (CN7.19 U16.53), Segment_LCD (U11.16)
COM1: STM32_microcontroller_IOs (CN7.23 U16.54), Segment_LCD (U11.15)
COM2: STM32_microcontroller_IOs (CN10.2 U16.55), Segment_LCD (U11.14)
COM3: STM32_microcontroller_IOs (CN7.5 U16.80), Segment_LCD (U11.13)
I2C_SCL: STM32_microcontroller_IOs (SB5.2), PERIPHERAL (R48.1 U15.1)
I2C_SDA: STM32_microcontroller_IOs (SB4.2), PERIPHERAL (R49.1 U15.6)
MCU.SWCLK: STM32_microcontroller_IOs (SB13.1 U16.61), STLINK_V2EC (5 pins)
MCU.SWDIO: STM32_microcontroller_IOs (SB3.1 U16.58), STLINK_V2EC (5 pins)
NRST: STM32_microcontroller_IOs (6 pins), STLINK_V2EC (CN2.10 CN4.12 JP5.1 U9.5), Arduino_Mikrobus_connectors (CN6.3)
PA11: STM32_microcontroller_IOs (SB8.2 U16.56), USB-C_Device (CN14.A7 CN14.B7 U18.3 U18.4)
PA12: STM32_microcontroller_IOs (SB7.2 U16.57), USB-C_Device (CN14.A6 CN14.B6 U18.1 U18.6)
PB1: STM32_microcontroller_IOs (CN10.26 U16.30), Segment_LCD (U11.3)
PB2: STM32_microcontroller_IOs (CN10.24 U16.31), PERIPHERAL (R37.1)
PB11: STM32_microcontroller_IOs (CN10.20 U16.36), Segment_LCD (U11.7)
PB12: STM32_microcontroller_IOs (SB23.2 U16.39), PERIPHERAL (R60.1)
PB13: STM32_microcontroller_IOs (SB22.2 U16.40), PERIPHERAL (C50.1)
PB14: STM32_microcontroller_IOs (CN10.30 U16.41), Segment_LCD (U11.8)
PB15: STM32_microcontroller_IOs (CN10.28 U16.42), Segment_LCD (U11.9)
PC2: STM32_microcontroller_IOs (CN7.37 U16.12), PERIPHERAL (SB10.2)
PC4: STM32_microcontroller_IOs (CN10.36 U16.27), Segment_LCD (U11.1)
PC5: STM32_microcontroller_IOs (CN10.8 U16.28), Segment_LCD (U11.2)
PC6: STM32_microcontroller_IOs (CN10.6 U16.49), Segment_LCD (U11.18)
PC8: STM32_microcontroller_IOs (CN10.4 U16.51), Segment_LCD (U11.19)
PC9: STM32_microcontroller_IOs (CN10.3 U16.52), Segment_LCD (U11.20)
PC10: STM32_microcontroller_IOs (CN7.3 U16.63), Segment_LCD (U11.21)
PC11: STM32_microcontroller_IOs (CN7.4 U16.64), Segment_LCD (U11.28)
PC13: STM32_microcontroller_IOs (CN7.25 U16.4), PERIPHERAL (R30.1)
PD0: STM32_microcontroller_IOs (CN7.21 U16.66), Segment_LCD (U11.22)
PD1: STM32_microcontroller_IOs (CN10.34 U16.67), Segment_LCD (U11.23)
PD3: STM32_microcontroller_IOs (CN10.1 U16.69), Segment_LCD (U11.24)
PD4: STM32_microcontroller_IOs (CN7.1 U16.70), Segment_LCD (U11.25)
PD5: STM32_microcontroller_IOs (CN7.2 U16.71), Segment_LCD (U11.26)
PD6: STM32_microcontroller_IOs (CN7.11 U16.72), Segment_LCD (U11.27)
PD8: STM32_microcontroller_IOs (CN10.12 U16.43), Segment_LCD (U11.10)
PD9: STM32_microcontroller_IOs (CN7.13 U16.44), Segment_LCD (U11.11)
PD10: STM32_microcontroller_IOs (SB11.2 U16.45), PERIPHERAL (C42.1)
PD11: STM32_microcontroller_IOs (SB9.2 U16.46), PERIPHERAL (R56.1)
PD12: STM32_microcontroller_IOs (CN7.8 U16.47), Segment_LCD (U11.12)
PD13: STM32_microcontroller_IOs (CN7.10 U16.48), Segment_LCD (U11.17)
PE7: STM32_microcontroller_IOs (CN7.12 U16.32), Segment_LCD (U11.4)
PE8: STM32_microcontroller_IOs (CN7.26 U16.33), Segment_LCD (U11.5)
PE9: STM32_microcontroller_IOs (CN7.28 U16.34), Segment_LCD (U11.6)
PF3-BOOT0: STM32_microcontroller_IOs (CN7.9 R50.1 U16.78), Power (SW1.4)

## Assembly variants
U083C: not fitted C10 C23 C24 C38 C38 C58 CN2 CN12 HW6 R7 R12 R30 R37 R38 R42 R43 R53 SB6 SB7 SB7 SB7 SB10 SB10 SB11 SB11 SB12 SB12 SB13 SB13 SB14 SB14 SB15 SB15 SB18 SB18 SB19 SB21 SB21 SB22 SB22 SB25 SB26 SB27 SB28 X3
